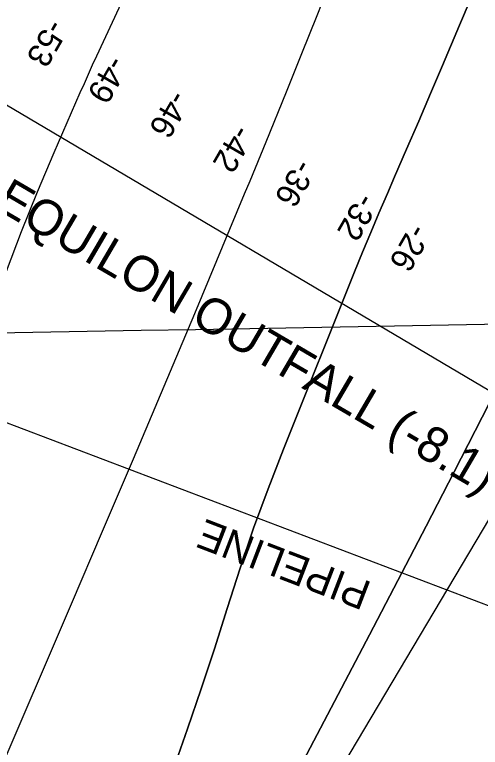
# Model space of a CAD drawing. Extents: x 3913936 to 3933962, y 195330 to 217741.
# Drawn here: x 3925651 to 3926306, y 205118 to 206148 of the extents above; entities that cross this region are included whole.
import ezdxf

# ---------------------------------------------------------------- set-up
doc = ezdxf.new("R2010")
doc.units = 0
for name, color, linetype in [('V-CHAN-NAID', 7, 'Continuous'), ('V-GRID-MAJR', 7, 'Continuous'), ('V-RIVR-RANG', 7, 'Continuous'), ('V-TOPO-DPTH', 7, 'Continuous'), ('V-TOPO-MAJR', 7, 'Continuous'), ('V-TOPO-MINR', 7, 'Continuous'), ('V-UTIL-IDEN', 7, 'Continuous'), ('V-UTIL-LINE', 7, 'Continuous')]:
    doc.layers.add(name, color=color, linetype=linetype)

msp = doc.modelspace()

# ---------------------------------------------------------------- linework, layer by layer
at = {"layer": 'V-GRID-MAJR'}
msp.add_spline([(3919352, 205590.8), (3919894.4, 205600.3), (3925219.4, 205693.6), (3930096.8, 205779.8)], degree=3, dxfattribs=at)
at = {"layer": 'V-TOPO-DPTH'}
for points in [[(3926651.5, 206280.4), (3926415.6, 205794.7), (3926401.1, 205765), (3926386.4, 205735.5), (3926371.6, 205706), (3926356.7, 205676.6), (3926308.3, 205582), (3926269, 205505.4), (3926229.5, 205429), (3926189.8, 205352.6), (3926149.9, 205276.3), (3925938.8, 204874.3), (3925929.3, 204856.1), (3925919.8, 204837.8), (3925910.5, 204819.5), (3925901.2, 204801.2), (3925836.6, 204673), (3925795.1, 204590.5), (3925753.8, 204507.9), (3925712.5, 204425.3)], [(3925624.7, 205072.5), (3925731.1, 205319.7), (3925774.7, 205421.7), (3925818.1, 205523.7), (3925861.2, 205625.9), (3925904.1, 205728.1), (3925974.3, 205896.3), (3925981.9, 205914.5), (3925989.4, 205932.8), (3925996.9, 205951.1), (3926004.4, 205969.3), (3926033.1, 206039.9), (3926054.7, 206093.5), (3926076.2, 206147.1), (3926097.4, 206200.9)], [(3925624.7, 205072.5), (3925731.1, 205319.7), (3925774.7, 205421.7), (3925818.1, 205523.7), (3925861.2, 205625.9), (3925904.1, 205728.1), (3925974.3, 205896.3), (3925981.9, 205914.5), (3925989.4, 205932.8), (3925996.9, 205951.1), (3926004.4, 205969.3), (3926033.1, 206039.9), (3926054.7, 206093.5), (3926076.2, 206147.1), (3926097.4, 206200.9)], [(3925874.1, 205087.8), (3925894, 205143.8), (3925913.3, 205200), (3925931.8, 205256.5), (3925949.7, 205313.1), (3925967.9, 205369.7), (3925987, 205425.9), (3926007.5, 205481.6), (3926028.9, 205537.1), (3926129, 205786.6), (3926140.2, 205814.2), (3926151.6, 205841.8), (3926163.2, 205869.3), (3926175, 205896.7), (3926185.2, 205920.2), (3926202.1, 205959.3), (3926219, 205998.4), (3926235.8, 206037.6), (3926252.5, 206076.8), (3926276.5, 206133.4), (3926305.1, 206200.9)], [(3926305.1, 206200.9), (3926276.5, 206133.4), (3926252.5, 206076.8), (3926235.8, 206037.6), (3926219, 205998.4), (3926202.1, 205959.3), (3926185.2, 205920.2), (3926175, 205896.7), (3926163.2, 205869.3), (3926151.6, 205841.8), (3926140.2, 205814.2), (3926129, 205786.6), (3926028.9, 205537.1), (3926007.5, 205481.6), (3925987, 205425.9), (3925967.9, 205369.7), (3925949.7, 205313.1), (3925931.8, 205256.5), (3925913.3, 205200), (3925894, 205143.8), (3925874.1, 205087.8)]]:
    msp.add_lwpolyline(points, dxfattribs=at)
at = {"layer": 'V-TOPO-MAJR'}
msp.add_lwpolyline([(3925639.7, 205787.3), (3925660.8, 205843.5), (3925683.3, 205899.2), (3925706.6, 205954.5), (3925743.2, 206038.6), (3925749, 206051.6), (3925754.7, 206064.6), (3925760.6, 206077.5), (3925766.5, 206090.4), (3925898.5, 206375.1), (3925946.6, 206478.9), (3925994.5, 206582.7), (3926042.2, 206686.7), (3926089.8, 206790.7), (3926160.1, 206944.5), (3926172.6, 206971.6), (3926185.3, 206998.5), (3926198.2, 207025.4)], dxfattribs=at)
at = {"layer": 'V-TOPO-MINR'}
for points in [[(3925712.5, 204425.3), (3925753.8, 204507.9), (3925795.1, 204590.5), (3925836.6, 204673), (3925901.2, 204801.2), (3925910.5, 204819.5), (3925919.8, 204837.8), (3925929.3, 204856.1), (3925938.8, 204874.3), (3926149.9, 205276.3), (3926189.8, 205352.6), (3926229.5, 205429), (3926269, 205505.4), (3926308.3, 205582), (3926356.7, 205676.6), (3926371.6, 205706), (3926386.4, 205735.5), (3926401.1, 205765), (3926415.6, 205794.7), (3926651.5, 206280.4)], [(3925624.7, 205072.5), (3925731.1, 205319.7), (3925774.7, 205421.7), (3925818.1, 205523.7), (3925861.2, 205625.9), (3925904.1, 205728.1), (3925974.3, 205896.3), (3925981.9, 205914.5), (3925989.4, 205932.8), (3925996.9, 205951.1), (3926004.4, 205969.3), (3926033.1, 206039.9), (3926054.7, 206093.5), (3926076.2, 206147.1), (3926097.4, 206200.9)], [(3925874.1, 205087.8), (3925894, 205143.8), (3925913.3, 205200), (3925931.8, 205256.5), (3925949.7, 205313.1), (3925967.9, 205369.7), (3925987, 205425.9), (3926007.5, 205481.6), (3926028.9, 205537.1), (3926129, 205786.6), (3926140.2, 205814.2), (3926151.6, 205841.8), (3926163.2, 205869.3), (3926175, 205896.7), (3926185.2, 205920.2), (3926202.1, 205959.3), (3926219, 205998.4), (3926235.8, 206037.6), (3926252.5, 206076.8), (3926276.5, 206133.4), (3926305.1, 206200.9)], [(3926015.1, 204928.3), (3926437.1, 205638.7), (3926451.7, 205664), (3926465.9, 205689.6), (3926479.5, 205715.6), (3926492.6, 205741.8), (3926679.5, 206126.2), (3926716.3, 206202.1)]]:
    msp.add_lwpolyline(points, dxfattribs=at)
at = {"layer": 'V-UTIL-LINE'}
for p, q in [((3926547, 205483.5), (3924936.8, 206437.1)), ((3924654.4, 205948.6), (3926575, 205219))]:
    msp.add_line(p, q, dxfattribs=at)

# ---------------------------------------------------------------- texts
at = {"layer": 'V-CHAN-NAID'}
msp.add_text('EQUILON OUTFALL (-8.1)', height=50, rotation=329.6517, dxfattribs=at).set_placement((3925620.8, 205876.9))
at = {"layer": 'V-RIVR-RANG'}
for s, p in [('-53', (3925698.9, 206144.1)), ('-49', (3925784.3, 206092.9)), ('-46', (3925871.3, 206044.2)), ('-42', (3925960.7, 205995.5)), ('-36', (3926047.9, 205947.2)), ('-32', (3926135.6, 205899.5)), ('-26', (3926209, 205856.4))]:
    msp.add_text(s, height=33.5, rotation=240.0512, dxfattribs=at).set_placement(p)
at = {"layer": 'V-UTIL-IDEN'}
msp.add_text(' PIPELINE', height=42, rotation=159.0125, dxfattribs=at).set_placement((3926169.3, 205343.7))

doc.saveas('drawing.dxf')
